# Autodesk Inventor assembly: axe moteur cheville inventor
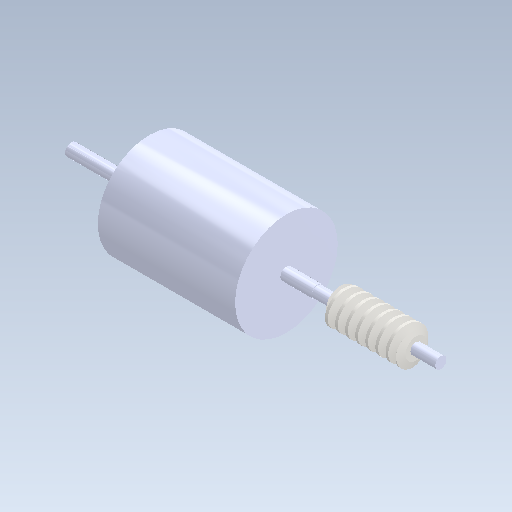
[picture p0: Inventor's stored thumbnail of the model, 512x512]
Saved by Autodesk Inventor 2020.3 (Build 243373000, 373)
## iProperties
Created: 2020-11
Part Number: axe moteur cheville inventor
Document SubType Name: Assembly
Designer: ficho
Mass: 13.0425 g
Surface Area: 34.615 cm^2
Volume: 10.1156 cm^3
Density: 1.28933 g/cm^3
Author: ficho
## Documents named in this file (3)
- D:\travail\année 2020-2021\2I2D\laveur de vitre\Lave vitre\4 Dossier Ressources\1 Modèles 3D Solidworks\adaptation inventor\axe moteur cheville inventor.iam
- D:\travail\année 2020-2021\2I2D\laveur de vitre\Lave vitre\4 Dossier Ressources\1 Modèles 3D Solidworks\adaptation inventor\Axe moteur Chenille.ipt
- D:\travail\année 2020-2021\2I2D\laveur de vitre\Lave vitre\4 Dossier Ressources\1 Modèles 3D Solidworks\adaptation inventor\Vis sans fin2.ipt
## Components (2 placed, 2 different names)
1. Axe moteur Chenille:1 — Placage:1, Affleurement:1
2. Vis sans fin:1 — Placage:1, Affleurement:1
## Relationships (2: Mate 1, Flush 1)
- Placage:1 [Mate]: Axe moteur Chenille:1 ↔ Vis sans fin:1
- Affleurement:1 [Flush]: Axe moteur Chenille:1 ↔ Vis sans fin:1
